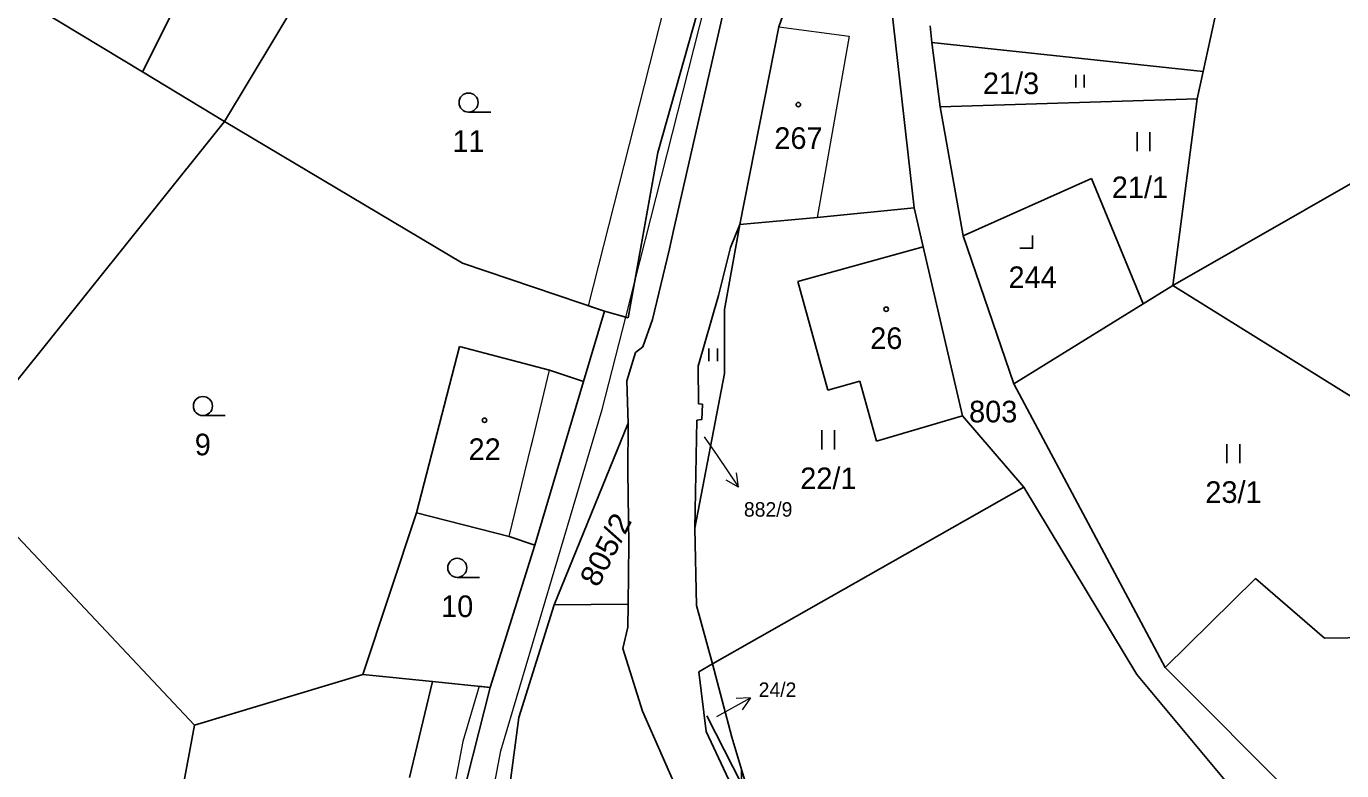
# Model space of a CAD drawing. Extents: x -739410 to -735662, y -942282 to -940043.
# Drawn here: x -738017.9 to -737914.5, y -941607.4 to -941548.9 of the extents above; entities that cross this region are included whole.
import ezdxf
from ezdxf.enums import TextEntityAlignment as Align

# ---------------------------------------------------------------- set-up
doc = ezdxf.new("R2010")
doc.units = 0
doc.header["$LTSCALE"] = 0.68
for name, color, linetype, lineweight in [('1', 7, 'Continuous', 25), ('13', 7, 'Continuous', 13), ('3', 7, 'Continuous', 25), ('4', 7, 'Continuous', 13), ('5', 7, 'Continuous', 25), ('7', 7, 'Continuous', 13)]:
    doc.layers.add(name, color=color, linetype=linetype, lineweight=lineweight)
doc.layers.add('2', color=7, linetype='Continuous')

msp = doc.modelspace()

# ---------------------------------------------------------------- linework, layer by layer
at = {"layer": '1'}
for p, q in [((-738008.8, -941552.44), (-738035.99, -941536)), ((-737992.08, -941539.27), (-738002.35, -941556.34)), ((-737925.36, -941552.42), (-737922.56, -941539.74)), ((-738008.8, -941552.44), (-738003.29, -941541.52)), ((-737963.27, -941541.12), (-737968.25, -941558.78)), ((-737927.73, -941569.24), (-737878.61, -941541.11)), ((-737967.02, -941564.92), (-737962.79, -941546.36)), ((-737958.13, -941547.19), (-737958.74, -941548.9)), ((-737948.08, -941563.14), (-737949.88, -941547.39)), ((-737958.74, -941548.9), (-737961.81, -941564.44)), ((-737946.84, -941548.83), (-737946.69, -941550.15)), ((-737946.69, -941550.15), (-737925.36, -941552.42)), ((-737946.69, -941550.15), (-737946.03, -941555.19)), ((-738002.35, -941556.34), (-738008.8, -941552.44)), ((-737925.82, -941554.57), (-737925.36, -941552.42)), ((-737946.03, -941555.19), (-737925.82, -941554.57)), ((-737946.03, -941555.19), (-737944.23, -941565.35)), ((-737927.73, -941569.24), (-737925.82, -941554.57)), ((-738023.97, -941583.33), (-738002.35, -941556.34)), ((-737983.63, -941567.5), (-738002.35, -941556.34)), ((-737970.59, -941571.78), (-737968.25, -941558.78)), ((-737944.23, -941565.35), (-737934.15, -941560.83)), ((-737934.15, -941560.83), (-737930.08, -941570.69)), ((-737955.72, -941563.9), (-737948.08, -941563.14)), ((-737948.08, -941563.14), (-737947.38, -941566.21)), ((-737963.01, -941571.13), (-737961.81, -941564.44)), ((-737961.81, -941564.44), (-737962.53, -941566.26)), ((-737961.81, -941564.44), (-737955.72, -941563.9)), ((-737967.33, -941566.37), (-737967.02, -941564.92)), ((-737944.23, -941565.35), (-737940.25, -941576.97)), ((-737962.53, -941566.26), (-737963.49, -941570.02)), ((-737947.38, -941566.21), (-737957.23, -941568.93)), ((-737947.38, -941566.21), (-737944.28, -941579.49)), ((-737972.46, -941571.26), (-737983.63, -941567.5)), ((-737957.23, -941568.93), (-737954.87, -941577.46)), ((-737927.73, -941569.24), (-737930.08, -941570.69)), ((-737927.73, -941569.24), (-737890.94, -941592.16)), ((-737963.49, -941570.02), (-737965.07, -941575.59)), ((-737930.08, -941570.69), (-737940.25, -941576.97)), ((-737974.09, -941576.78), (-737972.46, -941571.26)), ((-737972.46, -941571.26), (-737970.59, -941571.78)), ((-737963.01, -941576.16), (-737963.01, -941571.13)), ((-737987.24, -941587.11), (-737983.86, -941574.05)), ((-737983.86, -941574.05), (-737976.77, -941575.91)), ((-737970.68, -941576.74), (-737970.02, -941574.5)), ((-737970.02, -941574.5), (-737969.44, -941574.06)), ((-737965.07, -941575.59), (-737965.06, -941578.54)), ((-737977.92, -941589.66), (-737974.09, -941576.78)), ((-737976.77, -941575.91), (-737974.09, -941576.78)), ((-737970.58, -941580.08), (-737970.68, -941576.74)), ((-737963.01, -941576.16), (-737965.34, -941588.32)), ((-737954.87, -941577.46), (-737952.37, -941576.77)), ((-737952.37, -941576.77), (-737951.06, -941581.49)), ((-737940.25, -941576.97), (-737928.35, -941599.28)), ((-737965.06, -941578.54), (-737964.75, -941578.57)), ((-737964.75, -941578.57), (-737964.78, -941579.78)), ((-737965.18, -941579.82), (-737965.34, -941588.32)), ((-737964.78, -941579.78), (-737965.18, -941579.82)), ((-737951.06, -941581.49), (-737944.28, -941579.49)), ((-737944.28, -941579.49), (-737939.46, -941585.09)), ((-737970.58, -941580.08), (-737976.41, -941594.35)), ((-737970.62, -941583.83), (-737970.58, -941580.08)), ((-738004.7, -941603.8), (-738023.97, -941583.33)), ((-737970.53, -941589.59), (-737970.62, -941583.83)), ((-737963.96, -941599), (-737939.46, -941585.09)), ((-737939.46, -941585.09), (-737930.57, -941599.84)), ((-737987.24, -941587.11), (-737991.45, -941599.84)), ((-737979.94, -941588.97), (-737987.24, -941587.11)), ((-737965.34, -941588.32), (-737965.21, -941594.41)), ((-737977.92, -941589.66), (-737979.94, -941588.97)), ((-737981.44, -941600.84), (-737977.92, -941589.66)), ((-737970.59, -941594.29), (-737970.53, -941589.59)), ((-737921.23, -941592.29), (-737928.35, -941599.28)), ((-737915.82, -941596.97), (-737921.23, -941592.29)), ((-737976.41, -941594.35), (-737979.2, -941603.2)), ((-737976.41, -941594.35), (-737970.59, -941594.29)), ((-737970.61, -941596.11), (-737970.59, -941594.29)), ((-737965.21, -941594.41), (-737963.96, -941599)), ((-737906.67, -941596.84), (-737915.82, -941596.97)), ((-737965.04, -941599.61), (-737963.96, -941599)), ((-737964.46, -941604.3), (-737965.04, -941599.61)), ((-737963.96, -941599), (-737962.42, -941604.75)), ((-737928.35, -941599.28), (-737904.01, -941623.61)), ((-737991.45, -941599.84), (-738004.7, -941603.8)), ((-737991.45, -941599.84), (-737985.98, -941600.39)), ((-737985.98, -941600.39), (-737987.8, -941607.92)), ((-737981.44, -941600.84), (-737985.98, -941600.39)), ((-737930.57, -941599.84), (-737919.54, -941613.02)), ((-737989.79, -941633.54), (-737981.44, -941600.84)), ((-737964.75, -941613.38), (-737969.46, -941602.72)), ((-738004.7, -941603.8), (-738007.31, -941617.88)), ((-737979.2, -941603.2), (-737980.48, -941613.06)), ((-737959.28, -941615.34), (-737964.46, -941604.3)), ((-737962.42, -941604.75), (-737959.28, -941615.34))]:
    msp.add_line(p, q, dxfattribs=at)
for points in [[(-737969.44, -941574.06), (-737968.66, -941571.92), (-737967.33, -941566.37)], [(-737969.46, -941602.72), (-737971, -941597.78), (-737970.61, -941596.11)]]:
    msp.add_lwpolyline(points, dxfattribs=at)
at = {"layer": '13'}
for points in [[(-737973.73, -941570.83), (-737972.46, -941571.26), (-737970.78, -941571.73), (-737970.1, -941569.04), (-737968.25, -941558.78), (-737963.27, -941541.12), (-737962.29, -941535.26), (-737959.66, -941525.86), (-737958.87, -941519.98), (-737960.16, -941512.64), (-737962.64, -941508.83), (-737962.61, -941507.51), (-737963.66, -941506.35), (-737965.61, -941506), (-737965.78, -941509.69), (-737964.84, -941511.13), (-737963.1, -941513.8), (-737961.87, -941520.87), (-737964.56, -941534.7), (-737966.11, -941540.81)], [(-737961.57, -941535.45), (-737959.66, -941525.86), (-737962.29, -941535.26), (-737963.27, -941541.12), (-737968.25, -941558.78), (-737970.1, -941569.04)]]:
    msp.add_lwpolyline(points, close=True, dxfattribs=at)
msp.add_lwpolyline([(-737986.62, -941637.41), (-737980.6, -941605.83), (-737972.62, -941578.98), (-737970.78, -941571.73), (-737972.46, -941571.26), (-737974.09, -941576.78), (-737977.92, -941589.66), (-737981.44, -941600.84), (-737982.31, -941600.75), (-737983.6, -941605.1), (-737987.88, -941627.57)], dxfattribs=at)
at = {"layer": '3'}
for p, q in [((-737935.382, -941553.68), (-737935.382, -941552.675)), ((-737934.712, -941553.68), (-737934.712, -941552.675)), ((-737983.143, -941555.61), (-737981.393, -941555.61)), ((-737930.551, -941558.68), (-737930.551, -941557.18)), ((-737929.55, -941558.68), (-737929.55, -941557.18)), ((-737964.242, -941575.2), (-737964.242, -941574.195)), ((-737963.572, -941575.2), (-737963.572, -941574.195)), ((-738004.043, -941579.47), (-738002.293, -941579.47)), ((-737955.351, -941582.13), (-737955.351, -941580.63)), ((-737954.35, -941582.13), (-737954.35, -941580.63)), ((-737923.481, -941583.21), (-737923.481, -941581.71)), ((-737922.48, -941583.21), (-737922.48, -941581.71)), ((-737984.033, -941592.19), (-737982.283, -941592.19))]:
    msp.add_line(p, q, dxfattribs=at)
for points in [[(-737939.771, -941566.32), (-737938.77, -941566.32), (-737938.77, -941565.32)], [(-737964.392, -941603.066), (-737961.668, -941608.412), (-737961.665, -941607.314)]]:
    msp.add_lwpolyline(points, dxfattribs=at)
for centre in [(-737983.1429, -941554.8598), (-738004.0429, -941578.7198), (-737984.0329, -941591.4398)]:
    msp.add_circle(centre, 0.75, dxfattribs=at)
at = {"layer": '4'}
for p, q in [((-737978.1, -941581.39), (-737976.77, -941575.91)), ((-737979.94, -941588.97), (-737978.22, -941581.87)), ((-737978.22, -941581.87), (-737978.1, -941581.39))]:
    msp.add_line(p, q, dxfattribs=at)
msp.add_lwpolyline([(-737958.74, -941548.9), (-737953.19, -941549.64), (-737955.72, -941563.9)], dxfattribs=at)
at = {"layer": '5'}
for centre in [(-737957.1968, -941555.0192), (-737950.2868, -941571.1092), (-737981.8868, -941579.8392)]:
    msp.add_circle(centre, 0.175, dxfattribs=at)
at = {"layer": '7'}
for p, q in [((-737961.912, -941585.088), (-737962.057, -941583.978)), ((-737960.975, -941601.675), (-737962.094, -941601.723))]:
    msp.add_line(p, q, dxfattribs=at)
for points in [[(-737964.6, -941581.13), (-737963.59, -941582.6), (-737961.912, -941585.088), (-737962.887, -941584.538)], [(-737963.6, -941603.13), (-737960.975, -941601.675), (-737961.608, -941602.599)]]:
    msp.add_lwpolyline(points, dxfattribs=at)

# ---------------------------------------------------------------- texts
at = {"layer": '2'}
for s, p in [('21/3', (-737940.469, -941554.195)), ('11', (-737983.149, -941558.735)), ('267', (-737957.189, -941558.505)), ('21/1', (-737930.329, -941562.375)), ('244', (-737938.769, -941569.445)), ('26', (-737950.279, -941574.235)), ('803', (-737941.869, -941580.005)), ('9', (-738004.05, -941582.595)), ('22', (-737981.879, -941582.965)), ('22/1', (-737954.839, -941585.255)), ('23/1', (-737922.969, -941586.335)), ('10', (-737984.039, -941595.315))]:
    msp.add_text(s, height=1.7, dxfattribs=at).set_placement(p, align=Align.CENTER)
for s, p in [('882/9', (-737961.48, -941587.418)), ('24/2', (-737960.32, -941601.594))]:
    msp.add_text(s, height=1.139, dxfattribs=at).set_placement(p)
at = {"layer": '2', "width": 1.05}
msp.add_text('805/2', height=1.7, rotation=63, dxfattribs=at).set_placement((-737971.6003, -941590.3954), align=Align.CENTER)

doc.saveas('drawing.dxf')
